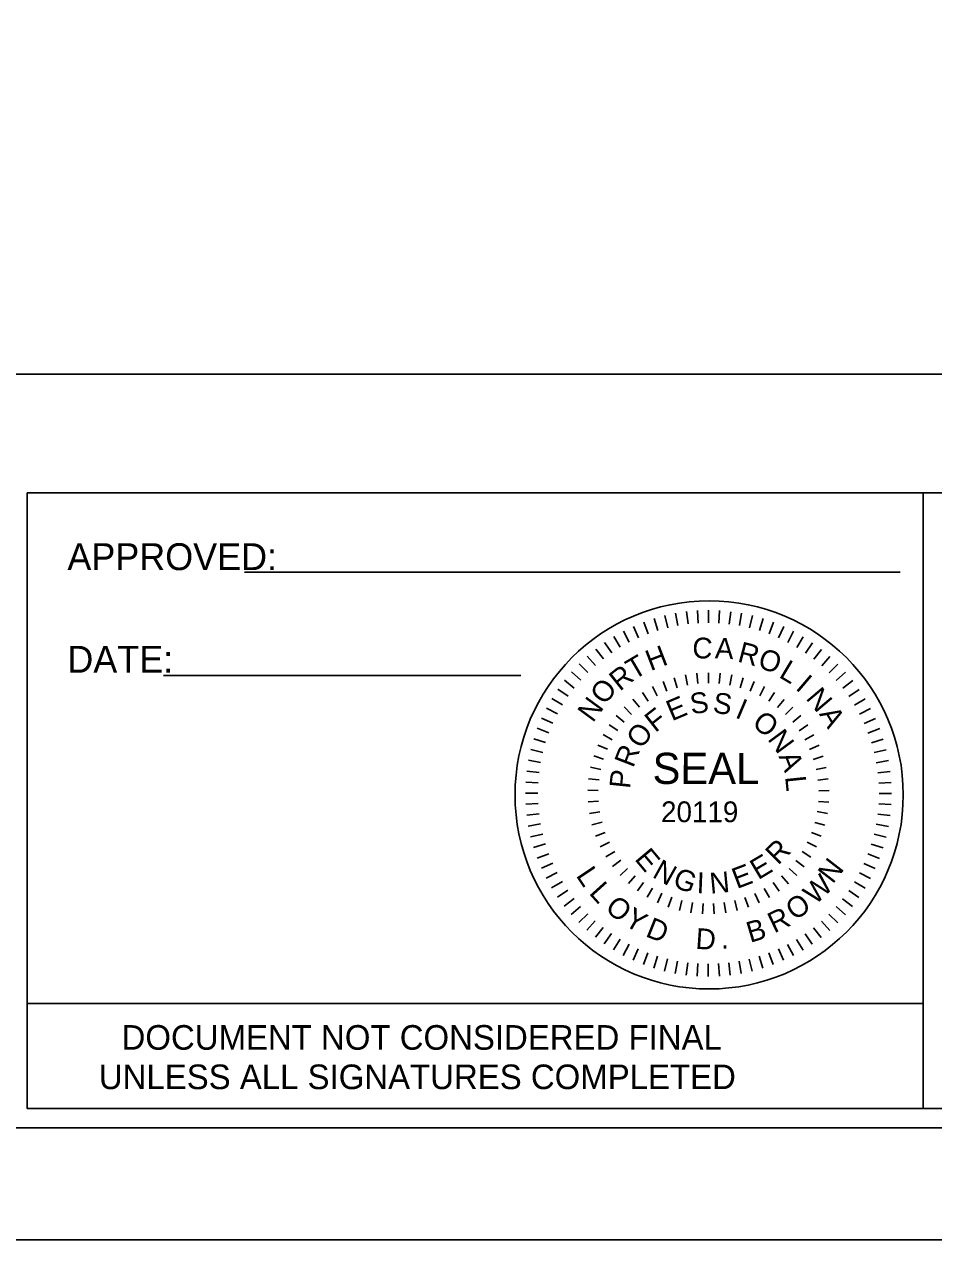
# Model space of a CAD drawing. Extents: x 768137 to 769825, y 651421 to 652521.
# Drawn here: x 769244.5 to 769447.5, y 651421.3 to 651692.7 of the extents above; entities that cross this region are included whole.
import ezdxf

# ---------------------------------------------------------------- set-up
doc = ezdxf.new("R2010")
doc.units = 0
for name, color, linetype in [('Default', 7, 'Continuous'), ('DEV BORDER CELL', 7, 'Continuous'), ('Scratch_Level_0', 7, 'Continuous'), ('Sheet Plot Border Outside CELL', 7, 'Continuous'), ('Sheet Sticker Exception Certification CELL', 7, 'Continuous')]:
    doc.layers.add(name, color=color, linetype=linetype)

msp = doc.modelspace()

# ---------------------------------------------------------------- linework, layer by layer
at = {"layer": 'Default'}
for p, q in [((769385.13, 651559.99), (769385.95, 651557.33)), ((769387.51, 651560.65), (769388.17, 651557.94)), ((769389.92, 651561.17), (769390.42, 651558.43)), ((769392.36, 651561.53), (769392.7, 651558.77)), ((769394.82, 651561.75), (769394.99, 651558.97)), ((769397.29, 651561.83), (769397.29, 651559.04)), ((769399.76, 651561.75), (769399.59, 651558.97)), ((769402.22, 651561.52), (769401.88, 651558.76)), ((769404.66, 651561.15), (769404.16, 651558.41)), ((769407.07, 651560.63), (769406.41, 651557.93)), ((769409.45, 651559.97), (769408.62, 651557.3)), ((769378.29, 651557.17), (769379.58, 651554.69)), ((769380.51, 651558.24), (769381.65, 651555.7)), ((769382.8, 651559.19), (769383.78, 651556.58)), ((769411.78, 651559.16), (769410.79, 651556.55)), ((769414.06, 651558.21), (769412.92, 651555.67)), ((769416.28, 651557.13), (769414.99, 651554.66)), ((769374.06, 651554.61), (769375.65, 651552.32)), ((769376.14, 651555.95), (769377.58, 651553.57)), ((769418.44, 651555.91), (769416.99, 651553.53)), ((769420.51, 651554.57), (769418.92, 651552.28)), ((769370.18, 651551.57), (769372.02, 651549.49)), ((769372.08, 651553.15), (769373.79, 651550.96)), ((769422.49, 651553.11), (769420.77, 651550.91)), ((769424.39, 651551.52), (769422.54, 651549.44)), ((769368.38, 651549.88), (769370.35, 651547.91)), ((769426.18, 651549.83), (769424.21, 651547.86)), ((769365.1, 651546.19), (769367.29, 651544.47)), ((769366.68, 651548.09), (769368.77, 651546.24)), ((769389.58, 651546.78), (769390.24, 651544.55)), ((769392.1, 651547.4), (769392.55, 651545.12)), ((769394.68, 651547.77), (769394.9, 651545.46)), ((769397.28, 651547.89), (769397.28, 651545.57)), ((769397.28, 651545.57), (769397.28, 651547.89)), ((769399.88, 651547.76), (769399.65, 651545.45)), ((769402.45, 651547.39), (769402.01, 651545.11)), ((769404.98, 651546.76), (769404.32, 651544.54)), ((769427.87, 651548.03), (769425.79, 651546.18)), ((769429.46, 651546.13), (769427.26, 651544.42)), ((769363.64, 651544.2), (769365.93, 651542.62)), ((769382.51, 651543.5), (769383.78, 651541.55)), ((769384.76, 651544.82), (769385.83, 651542.76)), ((769387.12, 651545.92), (769387.99, 651543.76)), ((769407.44, 651545.9), (769406.56, 651543.74)), ((769409.8, 651544.79), (769408.72, 651542.74)), ((769412.04, 651543.47), (769410.77, 651541.53)), ((769430.92, 651544.14), (769428.62, 651542.56)), ((769362.29, 651542.13), (769364.68, 651540.69)), ((769380.4, 651541.97), (769381.86, 651540.16)), ((769414.15, 651541.94), (769412.69, 651540.13)), ((769432.25, 651542.07), (769429.87, 651540.63)), ((769361.08, 651539.98), (769363.55, 651538.68)), ((769376.68, 651538.34), (769378.45, 651536.85)), ((769378.46, 651540.25), (769380.08, 651538.58)), ((769416.09, 651540.21), (769414.46, 651538.55)), ((769417.86, 651538.31), (769416.09, 651536.81)), ((769433.47, 651539.91), (769431, 651538.62)), ((769359.05, 651535.48), (769361.65, 651534.49)), ((769360, 651537.76), (769362.54, 651536.62)), ((769375.1, 651536.28), (769377.01, 651534.95)), ((769419.44, 651536.24), (769417.53, 651534.92)), ((769434.54, 651537.69), (769432, 651536.55)), ((769435.49, 651535.41), (769432.88, 651534.42)), ((769358.24, 651533.15), (769360.9, 651532.32)), ((769373.72, 651534.07), (769375.75, 651532.93)), ((769420.81, 651534.03), (769418.78, 651532.89)), ((769436.29, 651533.08), (769433.63, 651532.25)), ((769357.57, 651530.77), (769360.28, 651530.1)), ((769372.56, 651531.73), (769374.69, 651530.81)), ((769421.96, 651531.69), (769419.83, 651530.76)), ((769436.95, 651530.7), (769434.25, 651530.04)), ((769357.05, 651528.36), (769359.79, 651527.85)), ((769371.64, 651529.3), (769373.85, 651528.58)), ((769422.88, 651529.25), (769420.67, 651528.54)), ((769437.47, 651528.28), (769434.73, 651527.79)), ((769356.68, 651525.92), (769359.45, 651525.58)), ((769370.95, 651526.79), (769373.22, 651526.29)), ((769423.57, 651526.74), (769421.3, 651526.24)), ((769437.83, 651525.84), (769435.07, 651525.51)), ((769356.46, 651523.46), (769359.24, 651523.29)), ((769370.32, 651521.63), (769372.64, 651521.57)), ((769370.51, 651524.22), (769372.82, 651523.95)), ((769424, 651524.17), (769421.7, 651523.9)), ((769438.06, 651523.38), (769435.28, 651523.22)), ((769356.38, 651520.99), (769359.17, 651520.99)), ((769370.38, 651519.03), (769372.7, 651519.19)), ((769424.12, 651518.98), (769421.81, 651519.15)), ((769424.19, 651521.58), (769421.87, 651521.52)), ((769438.13, 651520.91), (769435.34, 651520.92)), ((769356.45, 651518.52), (769359.23, 651518.69)), ((769356.67, 651516.06), (769359.44, 651516.39)), ((769370.7, 651516.44), (769372.98, 651516.83)), ((769421.53, 651516.87), (769423.82, 651516.48)), ((769437.83, 651515.99), (769435.06, 651516.32)), ((769438.05, 651518.45), (769435.27, 651518.61)), ((769357.04, 651513.62), (769359.78, 651514.12)), ((769371.25, 651513.9), (769373.49, 651514.5)), ((769423.24, 651513.85), (769421, 651514.46)), ((769437.45, 651513.55), (769434.72, 651514.05)), ((769357.56, 651511.21), (769360.26, 651511.87)), ((769372.06, 651511.42), (769374.23, 651512.24)), ((769422.43, 651511.37), (769420.27, 651512.2)), ((769436.93, 651511.14), (769434.23, 651511.8)), ((769358.22, 651508.83), (769360.88, 651509.65)), ((769373.1, 651509.04), (769375.18, 651510.06)), ((769421.39, 651508.99), (769419.31, 651510.02)), ((769436.27, 651508.75), (769433.61, 651509.58)), ((769359.02, 651506.49), (769361.63, 651507.48)), ((769359.97, 651504.21), (769362.51, 651505.35)), ((769374.35, 651506.76), (769376.33, 651507.98)), ((769375.83, 651504.61), (769377.68, 651506.02)), ((769418.65, 651504.57), (769416.8, 651505.99)), ((769420.13, 651506.72), (769418.15, 651507.94)), ((769435.46, 651506.42), (769432.86, 651507.42)), ((769361.04, 651501.99), (769363.51, 651503.28)), ((769377.51, 651502.63), (769379.21, 651504.2)), ((769416.96, 651502.59), (769415.27, 651504.17)), ((769433.43, 651501.92), (769430.96, 651503.22)), ((769434.51, 651504.14), (769431.97, 651505.29)), ((769362.25, 651499.84), (769364.64, 651501.28)), ((769379.37, 651500.8), (769380.91, 651502.54)), ((769381.4, 651499.17), (769382.76, 651501.05)), ((769413.07, 651499.14), (769411.71, 651501.02)), ((769415.1, 651500.77), (769413.56, 651502.51)), ((769432.22, 651499.77), (769429.83, 651501.22)), ((769363.59, 651497.76), (769365.89, 651499.34)), ((769365.05, 651495.78), (769367.25, 651497.49)), ((769383.57, 651497.74), (769384.76, 651499.75)), ((769385.88, 651496.53), (769386.86, 651498.64)), ((769388.29, 651495.55), (769389.06, 651497.74)), ((769406.17, 651495.53), (769405.4, 651497.72)), ((769408.58, 651496.51), (769407.61, 651498.62)), ((769410.89, 651497.72), (769409.71, 651499.72)), ((769429.41, 651495.72), (769427.22, 651497.43)), ((769430.87, 651497.7), (769428.58, 651499.29)), ((769366.64, 651493.87), (769368.72, 651495.72)), ((769391.33, 651497.06), (769390.77, 651494.8)), ((769393.34, 651494.3), (769393.67, 651496.6)), ((769395.93, 651494.04), (769396.04, 651496.36)), ((769398.53, 651494.04), (769398.42, 651496.36)), ((769401.12, 651494.29), (769400.79, 651496.59)), ((769403.68, 651494.79), (769403.12, 651497.05)), ((769427.82, 651493.82), (769425.74, 651495.67)), ((769368.33, 651492.08), (769370.3, 651494.04)), ((769370.12, 651490.38), (769371.97, 651492.46)), ((769424.33, 651490.33), (769422.49, 651492.42)), ((769426.13, 651492.02), (769424.16, 651493.99)), ((769372.02, 651488.8), (769373.74, 651490.99)), ((769374, 651487.33), (769375.59, 651489.62)), ((769420.44, 651487.29), (769418.86, 651489.58)), ((769422.43, 651488.75), (769420.72, 651490.95)), ((769376.07, 651485.99), (769377.52, 651488.37)), ((769378.23, 651484.78), (769379.52, 651487.24)), ((769416.22, 651484.74), (769414.92, 651487.21)), ((769418.37, 651485.95), (769416.93, 651488.34)), ((769380.45, 651483.7), (769381.59, 651486.23)), ((769382.72, 651482.74), (769383.72, 651485.35)), ((769385.06, 651481.94), (769385.89, 651484.6)), ((769387.44, 651481.27), (769388.1, 651483.98)), ((769407, 651481.25), (769406.34, 651483.96)), ((769409.38, 651481.91), (769408.55, 651484.58)), ((769411.71, 651482.72), (769410.73, 651485.33)), ((769413.99, 651483.67), (769412.86, 651486.21)), ((769389.85, 651480.75), (769390.35, 651483.49)), ((769392.29, 651480.38), (769392.63, 651483.14)), ((769394.75, 651480.15), (769394.92, 651482.93)), ((769397.22, 651480.08), (769397.22, 651482.86)), ((769399.69, 651480.15), (769399.52, 651482.93)), ((769402.14, 651480.37), (769401.81, 651483.14)), ((769404.58, 651480.74), (769404.09, 651483.48))]:
    msp.add_line(p, q, dxfattribs=at)
at = {"layer": 'DEV BORDER CELL'}
for p, q in [((769293.7, 651570.37), (769440.04, 651570.37)), ((769445.19, 651564.55), (769445.19, 651450.55)), ((769275.58, 651547.29), (769355.37, 651547.29))]:
    msp.add_line(p, q, dxfattribs=at)
for points in [[(769800.34, 652496.28), (768300.34, 652496.28), (768300.34, 651446.28), (769800.34, 651446.28)], [(769245.15, 651588.05), (769445.19, 651588.05), (769445.19, 651450.55), (769245.15, 651450.55)], [(769445.19, 651588.05), (769559.19, 651588.05), (769559.19, 651450.55), (769445.19, 651450.55)]]:
    msp.add_lwpolyline(points, close=True, dxfattribs=at)
msp.add_circle((769397.41, 651520.61), 43.34, dxfattribs=at)
at = {"layer": 'Scratch_Level_0'}
msp.add_lwpolyline([(769750.34, 652446.28), (768350.34, 652446.28), (768350.34, 651496.28), (769229.19, 651496.28), (769229.19, 651614.55), (769750.34, 651614.55)], close=True, dxfattribs=at)
at = {"layer": 'Sheet Plot Border Outside CELL'}
msp.add_lwpolyline([(768137.34, 651421.28), (769825.34, 651421.28), (769825.34, 652521.28), (768137.34, 652521.28)], close=True, dxfattribs=at)
at = {"layer": 'Sheet Sticker Exception Certification CELL'}
for p, q in [((769245.15, 651450.55), (769245.15, 651474.05)), ((769245.15, 651474.05), (769445.19, 651474.05)), ((769445.19, 651474.04), (769445.19, 651450.54)), ((769445.19, 651450.55), (769245.15, 651450.55))]:
    msp.add_line(p, q, dxfattribs=at)

# ---------------------------------------------------------------- texts
at = {"layer": 'Default'}
for s, height, rotation, p in [('C', 4.64, 357.3039, (769393.57, 651551.19)), ('A', 4.64, 357.3039, (769398.64, 651551.1)), ('R', 4.64, 345.2946, (769403.56, 651550.41)), ('T', 4.64, 30.4466, (769380.6, 651546.2)), ('H', 4.64, 21.0146, (769384.33, 651548.22)), ('O', 4.64, 342.2378, (769408.05, 651549.07)), ('R', 4.64, 38.6075, (769377.47, 651543.61)), ('L', 4.64, 329.1015, (769412.77, 651547)), ('O', 4.64, 51.6643, (769374.11, 651540.49)), ('I', 4.64, 319.5261, (769416.51, 651544.3)), ('S', 4.64, 7.5951, (769393.44, 651538.6)), ('S', 4.64, 352.2989, (769398.08, 651538.98)), ('N', 4.64, 310.2316, (769418.83, 651542.11)), ('N', 4.64, 53.6237, (769371.44, 651536.57)), ('E', 4.64, 22.8914, (769389.08, 651537.01)), ('I', 4.64, 337.0026, (769403.01, 651537.97)), ('F', 4.64, 38.1876, (769385.37, 651534.39)), ('O', 4.64, 321.7064, (769406.75, 651536.16)), ('A', 4.64, 300.4641, (769421.89, 651538.68)), ('O', 4.64, 53.4838, (769382.28, 651530.65)), ('N', 4.64, 306.4101, (769410.32, 651533.05)), ('R', 4.64, 68.7801, (769380.44, 651526.48)), ('SEAL', 6.965, 359.947, (769384.78, 651523.05)), ('A', 4.64, 291.1139, (769412.86, 651529.25)), ('P', 4.64, 84.0763, (769379.73, 651521.88)), ('L', 4.64, 275.8176, (769414.36, 651524.66)), ('20119', 4.64, 359.947, (769386.67, 651514.52)), ('E', 4.64, 310.0171, (769380.61, 651506.23)), ('R', 4.64, 44.5119, (769412.78, 651504.77)), ('N', 4.64, 330.8721, (769384.5, 651502.36)), ('E', 4.64, 30.7408, (769408.36, 651501.54)), ('N', 4.64, 52.154, (769425, 651500.56)), ('L', 4.64, 303.882, (769367.56, 651502.6)), ('G', 4.64, 339.6384, (769389.04, 651500.18)), ('I', 4.64, 357.7332, (769394.57, 651498.69)), ('N', 4.64, 5.3628, (769397.72, 651498.53)), ('E', 4.64, 20.7549, (769403.6, 651499.56)), ('W', 4.64, 43.2714, (769421.1, 651495.9)), ('L', 4.64, 311.9538, (769370.43, 651498.62)), ('O', 4.64, 320.5966, (769373.95, 651494.96)), ('O', 4.64, 34.3888, (769416.53, 651492.42)), ('Y', 4.64, 329.2691, (769378.17, 651491.72)), ('R', 4.64, 25.5662, (769411.92, 651489.65)), ('D', 4.64, 338.2416, (769383, 651489.09)), ('B', 4.64, 16.5636, (769406.56, 651487.55)), ('D', 4.64, 356.0369, (769394.28, 651486.26)), ('.', 4.64, 3.7793, (769400.13, 651486.22))]:
    msp.add_text(s, height=height, rotation=rotation, dxfattribs=at).set_placement(p)
at = {"layer": 'DEV BORDER CELL'}
for s, p in [('APPROVED:  ', (769254.12, 651570.8)), ('DATE:  ', (769254.12, 651547.89))]:
    msp.add_text(s, height=6, dxfattribs=at).set_placement(p)
at = {"layer": 'Sheet Sticker Exception Certification CELL'}
for s, p in [('DOCUMENT NOT CONSIDERED FINAL', (769266.22, 651463.7)), ('UNLESS ALL SIGNATURES COMPLETED', (769261.15, 651454.9))]:
    msp.add_text(s, height=5.5, dxfattribs=at).set_placement(p)

doc.saveas('drawing.dxf')
